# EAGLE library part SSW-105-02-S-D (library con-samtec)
THROUGH-HOLE .025" SQ POST SOCKET Source: Samtec SSW.pdf
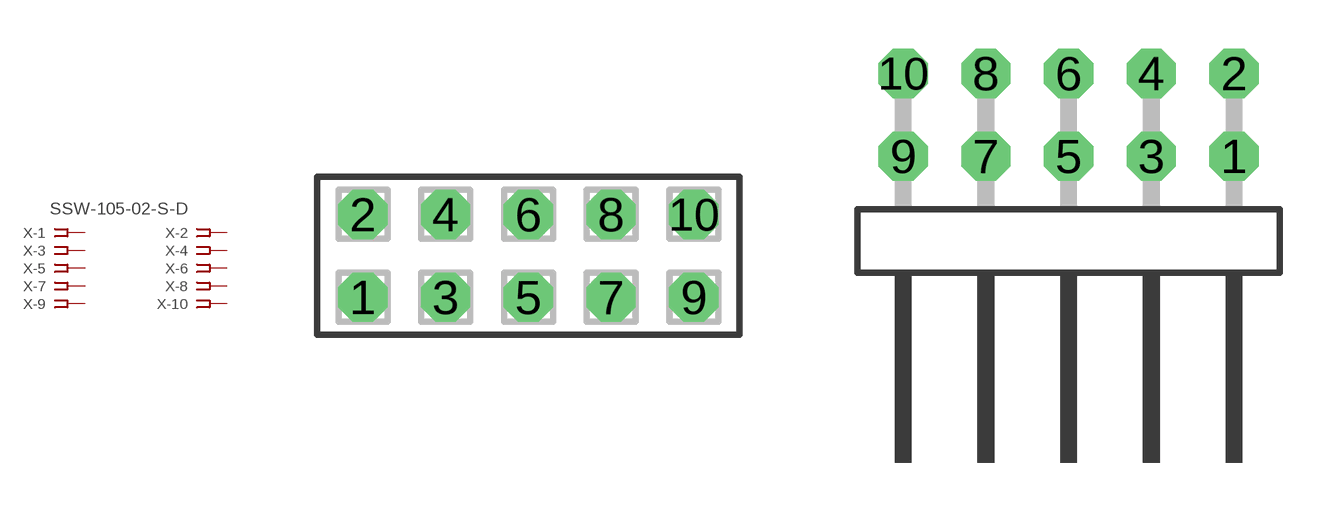
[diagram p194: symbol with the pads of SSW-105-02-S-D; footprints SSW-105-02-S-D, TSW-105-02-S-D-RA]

Designator prefix X; gates -1=FPINV -2=FPIN -3=FPIN -4=FPIN -5=FPIN -6=FPIN -7=FPIN -8=FPIN -9=FPIN -10=FPIN

## SSW-105-02-S-D (MPN: SSW-105-02-S-D; OC_FARNELL: unknown; OC_NEWARK: 11P9398)  [SSW-105-02-S-D]
1  -1:1  pas
2  -2:1  pas
3  -3:1  pas
4  -4:1  pas
5  -5:1  pas
6  -6:1  pas
7  -7:1  pas
8  -8:1  pas
9  -9:1  pas
10  -10:1  pas

## SSW-105-02-S-D-RA (MPN: SSW-105-02-S-D-RA; OC_FARNELL: unknown; OC_NEWARK: 18M6953)  [TSW-105-02-S-D-RA]
Pads as for SSW-105-02-S-D

## Footprint SSW-105-02-S-D (pad centres in mm)
THROUGH-HOLE .025" SQ POST SOCKET Source: Samtec SSW.pdf
drill 1 pad 1.5 octagon: 1 -5.08,-1.27; 2 -5.08,1.27; 3 -2.54,-1.27; 4 -2.54,1.27; 5 0,-1.27; 6 0,1.27; 7 2.54,-1.27; 8 2.54,1.27; 9 5.08,-1.27; 10 5.08,1.27

## Footprint TSW-105-02-S-D-RA (pad centres in mm)
THROUGH-HOLE .025" SQ POST HEADER Source: Samtec TSW.pdf
drill 1 pad 1.5 octagon: 1 5.08,1.524; 2 5.08,4.064; 3 2.54,1.524; 4 2.54,4.064; 5 0,1.524; 6 0,4.064; 7 -2.54,1.524; 8 -2.54,4.064; 9 -5.08,1.524; 10 -5.08,4.064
